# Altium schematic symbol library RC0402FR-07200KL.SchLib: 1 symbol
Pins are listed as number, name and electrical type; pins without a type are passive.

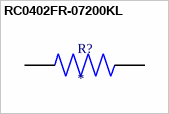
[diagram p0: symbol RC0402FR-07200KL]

## RC0402FR-07200KL
designator R?
200 kOhms Â±1% 0.063W, 1/16W Chip Resistor 0402 (1005 Metric) Moisture Resistant Thick Film; MF: Yageo; MP: RC0402FR-07200KL
footprint RESC1005X40N
pins: 1, 2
